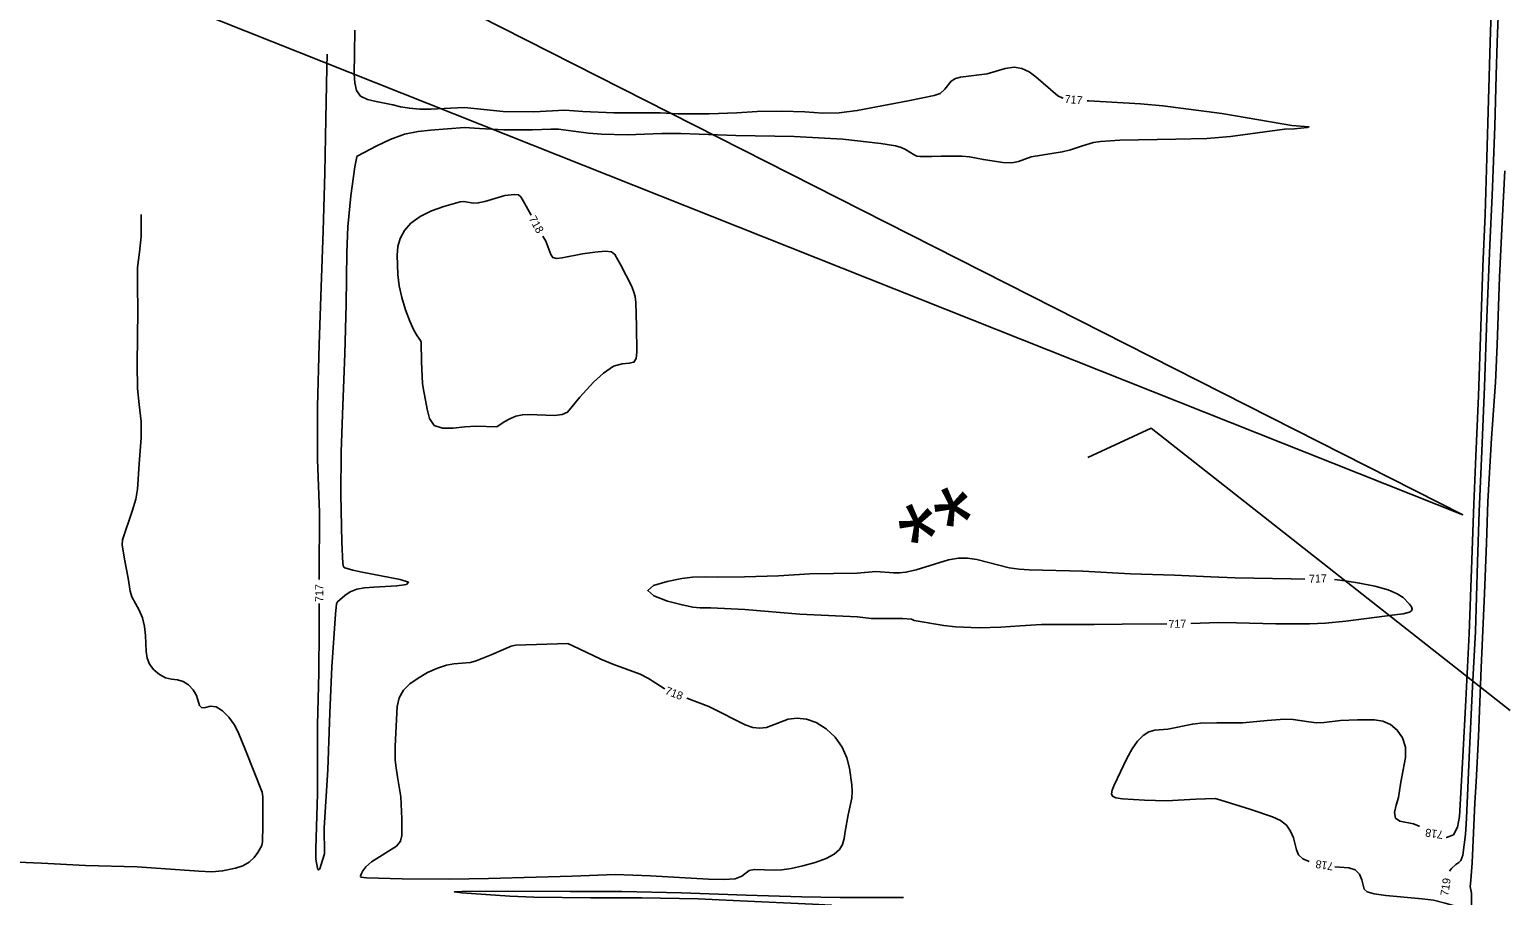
# Model space of a CAD drawing. Extents: x -310467766 to 17062430, y -322263100 to 8322522.
# Drawn here: x 1394957 to 1395694, y 572575 to 573008 of the extents above; entities that cross this region are included whole.
import ezdxf

# ---------------------------------------------------------------- set-up
doc = ezdxf.new("R2010")
doc.units = 0
for name, color, linetype in [('DT_X_Contour_Minor', 7, 'Continuous'), ('Level 19', 7, 'Continuous'), ('Level 40', 7, 'Continuous')]:
    doc.layers.add(name, color=color, linetype=linetype)

msp = doc.modelspace()

# ---------------------------------------------------------------- linework, layer by layer
at = {"layer": 'DT_X_Contour_Minor'}
for points in [[(1395691.83, 573036.82), (1395690.55, 573001.48), (1395690.06, 572985.16), (1395689.27, 572959.42), (1395688.05, 572925.03), (1395686.82, 572900.29), (1395685.28, 572863.83), (1395684.12, 572829.47), (1395682.77, 572797.27), (1395681.42, 572767.03), (1395680.65, 572741.73), (1395679.57, 572707.05), (1395678.19, 572679.56), (1395676.65, 572647.89), (1395675.23, 572613.77), (1395674.64, 572605.63), (1395673.29, 572595.32), (1395672.39, 572592.58), (1395671.32, 572591.73), (1395669.74, 572590.67), (1395667.58, 572588.65), (1395666.67, 572587.39)], [(1395688.03, 573032.03), (1395687.02, 573001.51), (1395686.07, 572972.81), (1395685.28, 572943.75), (1395684.42, 572915.52), (1395683.39, 572889.46), (1395682.27, 572859.42), (1395681.09, 572824.78), (1395679.85, 572794.66), (1395678.82, 572770.7), (1395677.61, 572738.24), (1395676.42, 572706.15), (1395674.79, 572672.7), (1395673.35, 572644.52), (1395671.71, 572614.63), (1395670.7, 572609.32), (1395668.61, 572605.45), (1395665.19, 572604.08), (1395664.99, 572604.11)], [(1395119.54, 573007.65), (1395119.38, 572995.93), (1395119.26, 572985.73), (1395119.49, 572981.26), (1395120.37, 572977.49), (1395122.41, 572974.67), (1395125.89, 572972.93), (1395130.23, 572971.91), (1395138.59, 572970.26), (1395142.44, 572969.34), (1395146.78, 572968.59), (1395152, 572968.15), (1395157.61, 572968.03), (1395167.39, 572968.57), (1395174.34, 572969.02), (1395193.63, 572966.89), (1395209.01, 572966.79), (1395224.5, 572967.56), (1395233.57, 572966.88), (1395248.96, 572966.29), (1395261.93, 572966.22), (1395272.09, 572966.25), (1395281.08, 572965.84), (1395296.67, 572965.74), (1395310.43, 572966.26), (1395320.58, 572967.01), (1395332.94, 572967.17), (1395344.53, 572966.71), (1395353.51, 572966.14), (1395361.54, 572966.25), (1395370.63, 572967.42), (1395396.07, 572972.23), (1395409.08, 572974.88)], [(1395101.75, 572733.08), (1395101.75, 572734.9), (1395101.85, 572766.59), (1395100.88, 572793.01), (1395100.96, 572819.53), (1395101.68, 572850.46), (1395102.74, 572879.28), (1395103.73, 572907.13), (1395104.5, 572936.25), (1395105.11, 572963.25), (1395105.54, 572988.72), (1395105.65, 572995.67)], [(1395409.08, 572974.88), (1395412.08, 572976.02), (1395414.43, 572978.03), (1395417.66, 572982.14), (1395419.76, 572983.38), (1395422.33, 572984.06), (1395435.56, 572985.71), (1395444.62, 572988.45), (1395449.06, 572989.09), (1395452.98, 572988.45), (1395456.5, 572986.7), (1395459.83, 572984.23), (1395470.9, 572974.7), (1395473.1, 572973.73), (1395473.62, 572973.63)], [(1395485.56, 572972.33), (1395486.32, 572972.27), (1395512.19, 572970.76), (1395523.45, 572969.75), (1395552.8, 572965.94), (1395571.36, 572962.78), (1395587.85, 572959.96), (1395596.38, 572959.2), (1395595.6, 572958.92), (1395589.17, 572958.35), (1395584.14, 572958.06), (1395557.2, 572954.4), (1395545.29, 572953.44), (1395529.85, 572953.14), (1395501.9, 572952.69), (1395492.22, 572952), (1395488.66, 572951.43), (1395483.15, 572949.79), (1395477.2, 572947.72), (1395473.08, 572946.77), (1395457.61, 572944.27), (1395451.17, 572941.91), (1395447.83, 572941.25), (1395443.36, 572941.38), (1395433.71, 572942.94), (1395426.72, 572944.25), (1395422.89, 572944.59), (1395412.61, 572944.66), (1395407.92, 572944.48)], [(1395407.92, 572944.48), (1395402.04, 572944.42), (1395400.4, 572944.68), (1395399.08, 572945.24), (1395394.78, 572947.96), (1395392.63, 572948.89), (1395389.82, 572949.71), (1395382.43, 572950.89), (1395363.48, 572953.04), (1395339.19, 572954.41), (1395309.97, 572954.89), (1395282.55, 572955.96), (1395272.97, 572956.03), (1395255.62, 572955.36), (1395242.76, 572955.68), (1395236.29, 572956.16), (1395221.31, 572958.04), (1395217.52, 572958.1), (1395208.34, 572957.7), (1395194.07, 572957.77), (1395181.89, 572958.43), (1395174.38, 572958.87), (1395157.34, 572957.57), (1395151.22, 572957), (1395144.41, 572955.56), (1395137.2, 572952.94), (1395130.46, 572949.82), (1395120.68, 572944.63), (1395120.48, 572944.29), (1395119.58, 572939.29), (1395117.57, 572924.8), (1395116.01, 572909.27), (1395115.54, 572896.46), (1395115.23, 572870.64), (1395114.57, 572845.86), (1395113.46, 572820.02), (1395112.69, 572796.8), (1395112.52, 572775.5), (1395113.05, 572751.65), (1395113.5, 572741.08), (1395113.84, 572739.48), (1395114.48, 572738.97), (1395118.54, 572737.78), (1395123.14, 572736.78), (1395142.24, 572733.12), (1395146.34, 572731.7), (1395145.28, 572730.6), (1395140.53, 572729.83), (1395129, 572729.2), (1395124.41, 572728.95), (1395120.51, 572728.26), (1395117.17, 572726.87), (1395114.47, 572725.15), (1395110.88, 572721.95), (1395110.45, 572720.86), (1395109.89, 572715.74), (1395108.12, 572689.45), (1395107.05, 572666.43), (1395106.08, 572638.03), (1395104.14, 572609.05), (1395104.33, 572595.99), (1395102.61, 572590.11), (1395101.99, 572588.46), (1395101.4, 572587.88), (1395100.86, 572588.84), (1395100.12, 572593.29), (1395100.08, 572598.46), (1395100.85, 572625.9), (1395100.92, 572641.27), (1395100.92, 572660.37), (1395101.58, 572686.37), (1395101.66, 572708.03), (1395101.7, 572721.08)], [(1395694.35, 572937.37), (1395692.98, 572911.63), (1395691.71, 572884.17), (1395690.47, 572850.3), (1395689.6, 572831.46), (1395687.63, 572803.65), (1395685.88, 572772.07), (1395685.08, 572751.22), (1395684.11, 572726.02), (1395682.53, 572689), (1395681.09, 572654.57), (1395680.01, 572632.01), (1395679.34, 572621.41), (1395677.96, 572591.44), (1395677.29, 572582.9), (1395677.03, 572579.63), (1395677.62, 572576.35), (1395677.65, 572570.5)], [(1395190.58, 572809.42), (1395179.94, 572809.64), (1395174.48, 572809.34), (1395168.72, 572808.74), (1395163.38, 572808.64), (1395159.24, 572810.05), (1395156.81, 572813.55), (1395155.64, 572818.12), (1395154.41, 572825.3), (1395153.78, 572827.78), (1395153.28, 572831.09), (1395152.89, 572841.79), (1395152.64, 572851.66), (1395152.29, 572852.59), (1395150.62, 572854.89), (1395149.09, 572857.63), (1395147.05, 572862.12), (1395144.87, 572867.81), (1395142.99, 572873.96), (1395141.77, 572879.9), (1395141.11, 572885.46), (1395140.73, 572895.18), (1395141.1, 572899.43), (1395142.21, 572903.48), (1395144.32, 572907.42), (1395147.59, 572911.14), (1395152.15, 572914.5), (1395157.93, 572917.33), (1395163.95, 572919.55), (1395172.21, 572921.85), (1395174.07, 572922.03), (1395178.69, 572921.08), (1395181.24, 572921.22), (1395184.53, 572922.02), (1395194.56, 572925), (1395199.27, 572925.53), (1395201.26, 572925.34), (1395202.43, 572924.36), (1395204.29, 572921.21), (1395207.72, 572915.07)], [(1395012.77, 572915.52), (1395012.75, 572904.41), (1395011.92, 572896.66), (1395010.89, 572888.95), (1395010.85, 572880.05), (1395011.06, 572867.54), (1395010.82, 572840.65), (1395010.92, 572828.47), (1395011.73, 572820.49), (1395012.73, 572812.04), (1395012.82, 572803.85), (1395011.81, 572790.93), (1395010.96, 572778.23), (1395010.02, 572773.21), (1395008.29, 572767.27), (1395003.5, 572752.88), (1395003.3, 572750.39), (1395004.48, 572743.27), (1395006.2, 572733.72), (1395007.18, 572727.17), (1395008.11, 572724.41), (1395011.68, 572717.83), (1395013.38, 572713.89), (1395014.42, 572709.54), (1395014.92, 572705.08), (1395015.31, 572697.07), (1395015.81, 572693.73), (1395016.99, 572690.7), (1395019.08, 572687.9), (1395021.84, 572685.57), (1395024.89, 572684.01), (1395027.93, 572683.33), (1395030.88, 572682.96), (1395033.72, 572682.18), (1395036.39, 572680.44), (1395038.68, 572677.94), (1395040.36, 572675.09), (1395041.98, 572670.1), (1395043, 572668.97), (1395044.82, 572669.14), (1395047.33, 572669.7), (1395050.3, 572669.44), (1395053.47, 572667.51), (1395056.53, 572664.32), (1395059.16, 572660.59), (1395061.19, 572656.86), (1395064.92, 572647.77), (1395073.16, 572626.87), (1395073.58, 572624.49), (1395073.61, 572610.21), (1395073.38, 572601.97), (1395073.02, 572600.21), (1395071.07, 572596.6), (1395069.25, 572594.13), (1395066.74, 572591.8), (1395063.53, 572590), (1395059.96, 572588.74), (1395053.47, 572587.42), (1395048.02, 572587.01), (1395041.64, 572587.39), (1395010.79, 572589.44), (1394984.88, 572590.21), (1394962.94, 572591.36), (1394951.07, 572591.88)], [(1395213.57, 572904.59), (1395214.94, 572902.14), (1395217.46, 572895.42), (1395218.5, 572893.93), (1395220.3, 572893.51), (1395223.23, 572893.9), (1395233.39, 572895.81), (1395239.55, 572896.69), (1395244.69, 572897.1), (1395247.82, 572896.75), (1395249.55, 572895.52), (1395252.53, 572890.14), (1395257.79, 572879.89), (1395258.89, 572877.18), (1395259.62, 572874.46), (1395260, 572871.42), (1395260.27, 572859.69), (1395260.55, 572846.65), (1395260.21, 572843.5), (1395259.02, 572841.62), (1395256.67, 572841.13), (1395253.23, 572840.92), (1395248.86, 572839.6), (1395243.85, 572836.22), (1395238.89, 572831.68), (1395232.04, 572824.23), (1395225.89, 572816.77), (1395223.16, 572815.54), (1395219.36, 572815.02), (1395210.59, 572815.28), (1395206.7, 572815.48), (1395203.26, 572815.38), (1395200.04, 572814.74), (1395196.93, 572813.44), (1395194.19, 572811.86), (1395190.58, 572809.42)], [(1395400.04, 572737.89), (1395416.22, 572742.83), (1395421.24, 572743.69), (1395425.8, 572743.72), (1395430.47, 572743.04), (1395446.55, 572738.98), (1395451.55, 572738.2), (1395456.63, 572737.84), (1395483.39, 572737.23), (1395507.3, 572735.87), (1395529.2, 572735.31), (1395547.43, 572734.44), (1395559.48, 572733.85), (1395587.58, 572733.42), (1395594.39, 572733.3)], [(1395399.08, 572712.6), (1395397.68, 572713.18), (1395393.25, 572713.61), (1395383.16, 572713.53), (1395377.68, 572713.59), (1395370.71, 572714.37), (1395359.71, 572714.94), (1395342.01, 572715.73), (1395314.41, 572718.01), (1395297.53, 572718.84), (1395292.12, 572718.87), (1395288.51, 572719.27), (1395283.12, 572720.34), (1395275.75, 572722.32), (1395268.93, 572724.87), (1395265.91, 572727.58), (1395268.84, 572730.06), (1395275.58, 572732.08), (1395282.93, 572733.5), (1395288.35, 572734.21), (1395294.77, 572734.35), (1395301.05, 572734.19), (1395314.33, 572734.35), (1395331.27, 572734.93), (1395347.01, 572735.94), (1395370.55, 572736.31), (1395379.92, 572737.08), (1395388.72, 572736.44), (1395391.74, 572736.37), (1395394.97, 572736.67), (1395400.04, 572737.89)], [(1395609.21, 572733.01), (1395614.54, 572732.44), (1395621.69, 572731.31), (1395629.32, 572729.74), (1395635.98, 572727.91), (1395640.57, 572725.96), (1395643.44, 572724.02), (1395646.69, 572720.67), (1395647.64, 572719.35), (1395647.98, 572718.27), (1395647.63, 572717.41), (1395646.66, 572716.74), (1395643.48, 572715.87), (1395639.32, 572715.37), (1395614.79, 572712.31), (1395604.74, 572711.31), (1395596.76, 572710.94), (1395579.81, 572710.92), (1395560.24, 572711.35), (1395551.36, 572711.52), (1395537.45, 572711.13)], [(1395525.45, 572710.89), (1395503.05, 572710.83), (1395489.08, 572710.58), (1395462.69, 572710.66), (1395452.05, 572709.96), (1395442.35, 572709.22), (1395431.56, 572708.95), (1395419.8, 572709.36), (1395413.87, 572710.04), (1395399.08, 572712.6)], [(1395285.48, 572673.81), (1395296.5, 572669.64), (1395301.82, 572667.02), (1395310.23, 572662.55), (1395314.65, 572660.5), (1395318.51, 572659.18), (1395321.93, 572658.72), (1395325.21, 572659.14), (1395336.17, 572663.24), (1395340.54, 572663.77), (1395345.23, 572663.27), (1395350.14, 572661.54), (1395355.08, 572658.46), (1395359.6, 572654.29), (1395363.18, 572649.35), (1395365.45, 572644.01), (1395366.71, 572638.76), (1395367.89, 572630.4), (1395368.09, 572627.18), (1395367.86, 572623.81), (1395366.12, 572615.46), (1395364.68, 572607.2), (1395364.18, 572603.71), (1395363.33, 572600.68), (1395361.75, 572598.08), (1395359.11, 572595.8), (1395355.08, 572593.7), (1395349.57, 572591.71), (1395343.41, 572589.98), (1395337.63, 572588.7), (1395333.01, 572588.03), (1395329.28, 572587.84), (1395319.25, 572588.21), (1395316.68, 572587.67), (1395312.96, 572584.8), (1395309.62, 572583.56), (1395303.96, 572583.11), (1395296.24, 572583.3), (1395267.36, 572584.98), (1395249.7, 572585.71), (1395228.16, 572584.86), (1395210.18, 572584.26), (1395186.3, 572583.64), (1395167.02, 572583.28), (1395143.19, 572583.53), (1395125.36, 572583.93), (1395122.54, 572584.36), (1395122.31, 572584.88), (1395122.64, 572585.85), (1395123.46, 572587.43), (1395125.08, 572589.51), (1395127.89, 572591.92), (1395140.3, 572599.77), (1395142.34, 572602.31), (1395143.05, 572605.16), (1395143.07, 572613.48), (1395142.49, 572624.42), (1395140.89, 572634.49), (1395140.15, 572638.88), (1395139.74, 572642.84), (1395139.7, 572649.87), (1395140.67, 572669.61), (1395141.78, 572673.95), (1395143.93, 572677.71), (1395147.09, 572680.94), (1395151.14, 572683.84), (1395155.88, 572686.52), (1395160.8, 572688.76), (1395165.35, 572690.29), (1395169.09, 572690.96), (1395177.33, 572691.58), (1395180.1, 572692.43), (1395187.6, 572695.5), (1395197.71, 572699.75), (1395199.91, 572700.25), (1395225.94, 572701.11)], [(1395225.94, 572701.11), (1395231.67, 572698.41), (1395242.5, 572693.26), (1395248.43, 572690.75), (1395262.21, 572685.84), (1395266.39, 572683.53), (1395274.09, 572678.61), (1395274.41, 572678.45)], [(1395651.71, 572609.73), (1395651.52, 572609.85), (1395648.67, 572611.05), (1395641.86, 572612.36), (1395639.65, 572613.83), (1395639.24, 572616.64), (1395640.04, 572620.31), (1395641.13, 572624.09), (1395642.22, 572630.78), (1395642.82, 572634.54), (1395644.65, 572644.2), (1395644.62, 572649.3), (1395643.19, 572653.97), (1395640.57, 572657.86), (1395637.17, 572660.67), (1395633.32, 572662.24), (1395629.21, 572662.87), (1395620.64, 572663.03), (1395612.13, 572662.64), (1395604.03, 572661.64), (1395600.15, 572661.51), (1395596.35, 572661.93), (1395588.49, 572663.15), (1395584.19, 572663.24), (1395575.45, 572662.54), (1395563.32, 572661.51), (1395550.36, 572661.45), (1395542.22, 572661.31), (1395538.14, 572660.86), (1395525.82, 572658.35), (1395519.33, 572657.76), (1395516.44, 572656.95), (1395513.59, 572655.17), (1395510.77, 572652.34), (1395508, 572648.46), (1395505.32, 572643.67), (1395499.1, 572630.34), (1395498.06, 572627.73), (1395497.69, 572625.93), (1395498.15, 572624.73), (1395499.83, 572623.97), (1395503.19, 572623.49), (1395514.18, 572622.88), (1395525.13, 572622.54), (1395539.95, 572623.32), (1395549.54, 572623.6), (1395552.34, 572622.85), (1395566.87, 572618.35), (1395578.18, 572614.47), (1395582.16, 572612.57), (1395585.12, 572610.26), (1395587.22, 572607.3), (1395588.63, 572603.99), (1395590.2, 572597.94), (1395591.25, 572595.55), (1395593.41, 572593.52), (1395596.58, 572592.08)], [(1395609.37, 572589.53), (1395616.34, 572589), (1395619.58, 572587.93), (1395621.67, 572585.75), (1395622.85, 572582.96), (1395624.08, 572578.35), (1395625.55, 572577), (1395628.97, 572576), (1395634.9, 572575.13), (1395652.96, 572573.5), (1395658.58, 572572.82), (1395664.55, 572571.4), (1395669.17, 572569.99), (1395670.37, 572569.38)], [(1395393.8, 572574.21), (1395362.17, 572574.14), (1395343.03, 572574.51), (1395315.06, 572575.29), (1395282.77, 572576.55), (1395252.93, 572577.15), (1395227.41, 572577.18), (1395196.29, 572577.27), (1395173.12, 572577.21), (1395169.35, 572576.95), (1395172.99, 572576.45), (1395196.98, 572574.82), (1395208.99, 572574.39), (1395237.42, 572574.02), (1395263.05, 572573.99), (1395291.1, 572573.44), (1395312.14, 572572.47), (1395348.26, 572570.8), (1395357.64, 572570.32), (1395359.48, 572568.92), (1395362.36, 572567.86), (1395368.03, 572566.96), (1395376.99, 572566.46), (1395393.5, 572566.27)]]:
    msp.add_lwpolyline(points, dxfattribs=at)
at = {"layer": 'Level 40'}
for p in [(1395485.95, 572794.04), (1395697.04, 572667.55)]:
    msp.add_line(p, (1395517.5, 572808.75), dxfattribs=at)
msp.add_lwpolyline([(1394793.59, 573115.01), (1395673.26, 572765.45), (1394892.55, 573161.15)], close=True, dxfattribs=at)

# ---------------------------------------------------------------- texts
at = {"layer": 'Level 19'}
for s, rotation, p in [('717', 355.18227, (1395474.17, 572971.28)), ('718', 299.19283, (1395206.34, 572913.43)), ('717', 1.59855, (1395596.49, 572731.45)), ('717', 89.79394, (1395103.71, 572721.81)), ('717', 1.59855, (1395526.25, 572708.82)), ('718', 339.07069, (1395274.26, 572675.95)), ('718', 171.38454, (1395663.7, 572607.34)), ('718', 171.38454, (1395608.86, 572591.58)), ('719', 81.38454, (1395665.99, 572574.74))]:
    msp.add_text(s, height=4, rotation=rotation, dxfattribs=at).set_placement(p)
at = {"layer": 'Level 40'}
msp.add_text('**', height=37.5, rotation=25, dxfattribs=at).set_placement((1395403.42, 572732.04))

doc.saveas('drawing.dxf')
